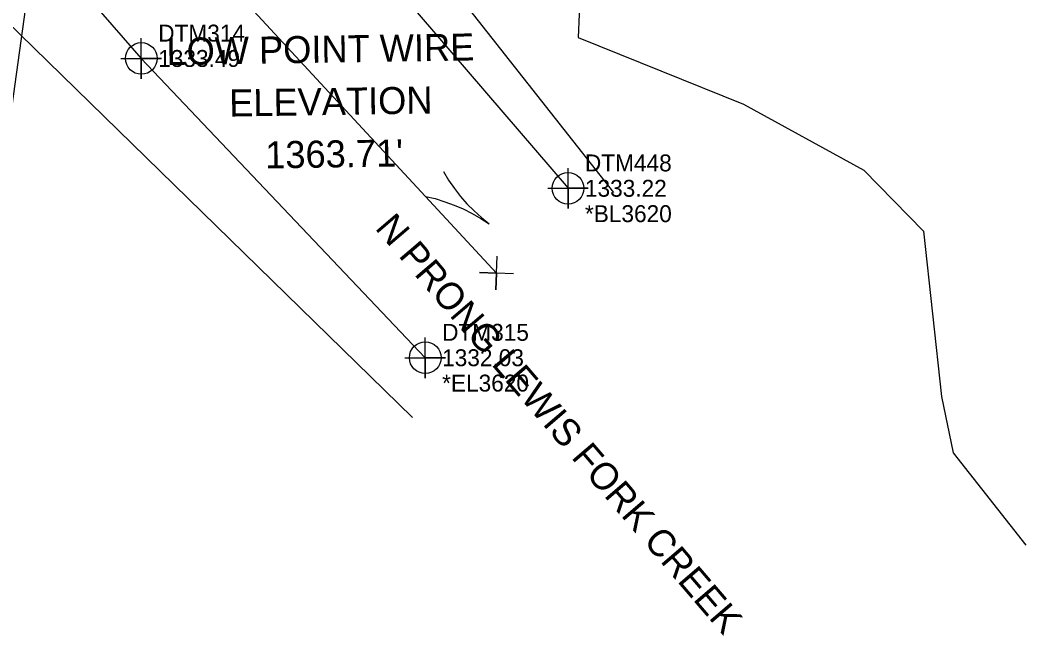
# Model space of a CAD drawing. Extents: x 1303760 to 1305114, y 904598 to 905144.
# Drawn here: x 1304338.5 to 1304487, y 904659.7 to 904750.7 of the extents above; entities that cross this region are included whole.
import ezdxf

# ---------------------------------------------------------------- set-up
doc = ezdxf.new("R2010")
doc.units = 0
for name, color, linetype in [('Exist Hydro Jurisdictional Stream or Body of Water', 7, 'Continuous'), ('Exist Hydro Jurisdictional Stream or Body of Water Text', 7, 'Continuous'), ('Exist Hydro Stream Flow Arrow CELL', 7, 'Continuous'), ('Exist Hydro Stream or Body of Water Cogo Comment', 7, 'Continuous'), ('Exist Hydro Stream or Body of Water Cogo Elevation', 7, 'Continuous'), ('Exist Hydro Stream or Body of Water Cogo Number', 7, 'Continuous'), ('Exist Hydro Stream or Body of Water Cogo Point CELL', 7, 'Continuous'), ('Exist Property Corner CELL', 7, 'Continuous'), ('Exist Property Line', 7, 'Continuous'), ('Exist Utilities Other Located Object Leader', 7, 'Continuous'), ('Exist Utilities Other Located Object Text', 7, 'Continuous'), ('Exist Vegetation Woods Line', 7, 'Continuous')]:
    doc.layers.add(name, color=color, linetype=linetype)

msp = doc.modelspace()

# ---------------------------------------------------------------- linework, layer by layer
at = {"layer": 'Exist Hydro Jurisdictional Stream or Body of Water'}
for points in [[(1304312.92, 904805.96), (1304319.68, 904787.16), (1304356.37, 904745.03), (1304398.3, 904700.8)], [(1304342.79, 904805.02), (1304344.86, 904801.75), (1304365.18, 904788.65), (1304380.39, 904768.97), (1304394.99, 904754.33), (1304419.39, 904725.84)]]:
    msp.add_lwpolyline(points, dxfattribs=at)
at = {"layer": 'Exist Hydro Stream Flow Arrow CELL'}
msp.add_line((1304403.72, 904723.52), (1304403.72, 904723.52), dxfattribs=at)
for points in [[(1304401.02, 904728.31), (1304401.75, 904727.04), (1304402.63, 904725.83), (1304403.51, 904724.65), (1304404.47, 904723.56), (1304405.52, 904722.51), (1304406.63, 904721.51), (1304407.77, 904720.59)], [(1304398.33, 904724.61), (1304399.76, 904724.31), (1304401.19, 904723.85), (1304402.59, 904723.37), (1304403.92, 904722.79), (1304405.24, 904722.13), (1304406.54, 904721.39), (1304407.77, 904720.59)]]:
    msp.add_lwpolyline(points, dxfattribs=at)
at = {"layer": 'Exist Hydro Stream or Body of Water Cogo Point CELL'}
for points in [[(1304353.37, 904745.03), (1304359.37, 904745.03), (1304356.37, 904745.03), (1304356.37, 904742.03), (1304356.37, 904748.03)], [(1304416.39, 904725.84), (1304422.39, 904725.84), (1304419.39, 904725.84), (1304419.39, 904722.84), (1304419.39, 904728.84)], [(1304395.3, 904700.8), (1304401.3, 904700.8), (1304398.3, 904700.8), (1304398.3, 904697.8), (1304398.3, 904703.8)]]:
    msp.add_lwpolyline(points, dxfattribs=at)
for centre in [(1304356.37, 904745.03), (1304419.39, 904725.84), (1304398.3, 904700.8)]:
    msp.add_circle(centre, 2.34, dxfattribs=at)
at = {"layer": 'Exist Property Corner CELL'}
msp.add_line((1304408.84, 904713.32), (1304408.84, 904713.32), dxfattribs=at)
msp.add_lwpolyline([(1304411.34, 904713.22), (1304406.34, 904713.41), (1304408.84, 904713.32), (1304408.75, 904710.82), (1304408.94, 904715.82)], dxfattribs=at)
at = {"layer": 'Exist Property Line'}
msp.add_line((1304368.38, 904757), (1304408.84, 904713.32), dxfattribs=at)
at = {"layer": 'Exist Utilities Other Located Object Leader'}
msp.add_line((1304346.86, 904807.85), (1304336.83, 904734.83), dxfattribs=at)
at = {"layer": 'Exist Vegetation Woods Line'}
for points in [[(1304214.49, 904670.67), (1304223.46, 904712.45), (1304241.79, 904731.19), (1304279.23, 904744.08), (1304302.63, 904753.84), (1304307.7, 904771.41), (1304284.69, 904785.85), (1304278.06, 904793.66), (1304286.25, 904802.64), (1304305.75, 904801.08), (1304330.13, 904756.77), (1304396.43, 904691.95)], [(1304426.16, 904725.22), (1304402.13, 904755.75), (1304398.9, 904761.14), (1304366.25, 904790.59), (1304399.98, 904787.72), (1304438.9, 904784.94), (1304461.09, 904787.92), (1304439.98, 904775.2), (1304421.94, 904772.32), (1304420.91, 904748.11), (1304445.31, 904738.26), (1304463.08, 904728.53), (1304471.89, 904719.5), (1304474.56, 904695.08), (1304476.25, 904686.72), (1304487.01, 904673.07)]]:
    msp.add_lwpolyline(points, dxfattribs=at)

# ---------------------------------------------------------------- texts
at = {"layer": 'Exist Hydro Jurisdictional Stream or Body of Water Text'}
msp.add_text('N PRONG LEWIS FORK CREEK', height=4, rotation=310.5725, dxfattribs=at).set_placement((1304390.77, 904719.91))
at = {"layer": 'Exist Hydro Stream or Body of Water Cogo Comment'}
for s, p in [('*BL3620', (1304421.89, 904720.84)), ('*EL3620', (1304400.8, 904695.8))]:
    msp.add_text(s, height=2.5, dxfattribs=at).set_placement(p)
at = {"layer": 'Exist Hydro Stream or Body of Water Cogo Elevation'}
for s, p in [('1333.49', (1304358.87, 904743.78)), ('1333.22', (1304421.89, 904724.59)), ('1332.03', (1304400.8, 904699.55))]:
    msp.add_text(s, height=2.5, dxfattribs=at).set_placement(p)
at = {"layer": 'Exist Hydro Stream or Body of Water Cogo Number'}
for s, p in [('DTM314', (1304358.87, 904747.53)), ('DTM448', (1304421.89, 904728.34)), ('DTM315', (1304400.8, 904703.3))]:
    msp.add_text(s, height=2.5, dxfattribs=at).set_placement(p)
at = {"layer": 'Exist Utilities Other Located Object Text'}
for s, p in [('LOW POINT WIRE ', (1304360.12, 904744.05)), ('ELEVATION', (1304369.38, 904736.44)), ("1363.71'", (1304374.7, 904728.77))]:
    msp.add_text(s, height=4, rotation=0.8742, dxfattribs=at).set_placement(p)

doc.saveas('drawing.dxf')
